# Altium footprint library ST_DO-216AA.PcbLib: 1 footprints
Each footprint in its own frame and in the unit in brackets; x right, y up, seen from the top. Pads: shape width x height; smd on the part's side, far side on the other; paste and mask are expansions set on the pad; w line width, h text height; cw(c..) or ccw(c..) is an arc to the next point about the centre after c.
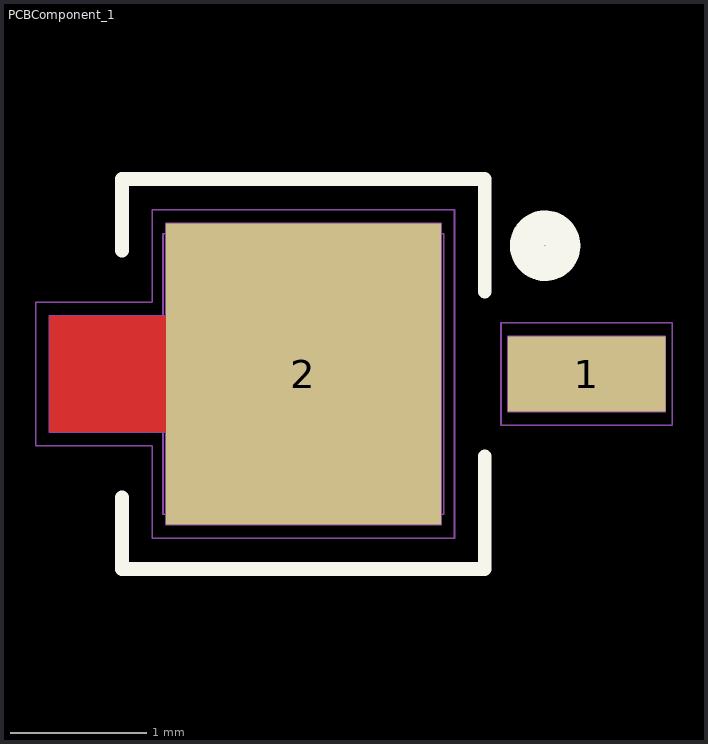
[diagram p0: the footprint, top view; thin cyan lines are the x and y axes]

## PCBComponent_1 [mm]
pads (2):
  rect 1.15x0.55 smd paste-20 mask+0.1: 1(-1265.846,-1268.525)
  rect 2.01x2.2 smd paste-20 mask+0.1: 2(-1267.916,-1268.525)
Top Layer:
  rectangle: -1269.771,-1268.95 -1268.768,-1268.1
Top Overlay:
  circle w0.254: c-1266.149,-1267.587 r0.131
  lines w0.1: -1269.241,-1269.425 -1269.241,-1269.95 -1266.591,-1269.95 -1266.591,-1269.125 ; -1269.241,-1267.625 -1269.241,-1267.1 -1266.591,-1267.1 -1266.591,-1267.925
Top Paste:
  rectangle: -1268.871,-1269.575 -1266.961,-1267.475
  rectangle: -1269.721,-1268.9 -1268.871,-1268.15
  rectangle: -1266.421,-1268.8 -1265.271,-1268.25
Top Solder:
  rectangle: -1269.871,-1269.05 -1268.941,-1268
Mechanical 1:
  lines w0.013: -1268.416,-1268.525 -1267.416,-1268.525 ; -1267.916,-1269.025 -1267.916,-1268.025 ; -1268.941,-1269.55 -1268.941,-1267.5 -1266.891,-1267.5 -1266.891,-1269.55 -1268.941,-1269.55 ; -1267.398,-1269.55 -1267.398,-1267.5 -1267.176,-1267.5 -1267.176,-1269.55 -1267.398,-1269.55
Mechanical 7:
  lines w0.013: -1269.871,-1269.05 -1269.021,-1269.05 -1269.021,-1269.725 -1266.811,-1269.725 -1266.811,-1267.325 -1269.021,-1267.325 -1269.021,-1268 -1269.871,-1268 -1269.871,-1269.05 ; -1266.471,-1268.9 -1266.471,-1268.15 -1265.221,-1268.15 -1265.221,-1268.9 -1266.471,-1268.9
Mechanical 34:
  lines w0.013: -1269.771,-1268.95 -1268.921,-1268.95 -1268.921,-1269.625 -1266.911,-1269.625 -1266.911,-1267.425 -1268.921,-1267.425 -1268.921,-1268.1 -1269.771,-1268.1 -1269.771,-1268.95 ; -1266.421,-1268.8 -1266.421,-1268.25 -1265.271,-1268.25 -1265.271,-1268.8 -1266.421,-1268.8
Mechanical 45:
  lines w0: -1265.846,-1268.8 -1265.846,-1268.25
  lines w0.013: -1269.721,-1268.9 -1268.871,-1268.9 -1268.871,-1269.575 -1266.961,-1269.575 -1266.961,-1267.475 -1268.871,-1267.475 -1268.871,-1268.15 -1269.721,-1268.15 -1269.721,-1268.9 ; -1266.421,-1268.8 -1266.421,-1268.25 -1265.271,-1268.25 -1265.271,-1268.8 -1266.421,-1268.8
Mechanical 51:
  text "1" at -1265.018,-1268.584 h0.2
  text "2" at -1269.987,-1268.525 h0.2
Mechanical 53:
  lines w0.013: -1268.941,-1269.55 -1268.941,-1267.5 -1266.891,-1267.5 -1266.891,-1269.55 -1268.941,-1269.55
3D body "ST Mite.STEP": height 1.1, standoff 0, extent -1269.431,-1269.475 -1265.631,-1267.575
